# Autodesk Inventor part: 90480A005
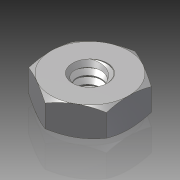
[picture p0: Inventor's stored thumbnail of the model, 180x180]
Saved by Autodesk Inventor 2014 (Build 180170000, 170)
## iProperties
Created: 2015-07
Part Number: 90480A005
Material: Steel
Document SubType Name: Modeling
Designer: Brad Factor
Density: 7.85 g/cm^3
Appearance: Steel
Author: Brad Factor
Title: 90480A005.step
Description: STEP AP203
Creation Date: 2015-02-23
Sending System: SolidWorks 2010
Preprocessor: SwSTEP 2.0
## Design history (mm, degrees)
node "90480A0051"
node "Mirror1"
node "Base1"
